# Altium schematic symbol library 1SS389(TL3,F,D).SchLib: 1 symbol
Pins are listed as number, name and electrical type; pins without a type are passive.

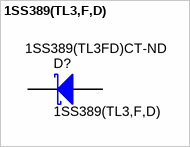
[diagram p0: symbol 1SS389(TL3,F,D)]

## 1SS389(TL3,F,D)
designator D?  Supplier Part Number: 1SS389(TL3FD)CT-ND
DIODE SCHOTTKY 10V 0.1A ESC; Manufacturer: Toshiba Semiconductor and Storage; U/M: EA; Vf_V: 0.38; Value: 500mV @ 100mA; Value1: 0.03A; Value2: 0.38V; Io_A: 100mA; TJmax_C: 125; Current - Reverse Leakage @ Vr: 20µA @ 10V; Speed: Small Signal =< 200mA (Io), Any Speed; Capacitance @ Vr, F: 40pF @ 0V, 1MHz
signal-integrity model Diode
footprint SOD-523 (NXP Semiconductor recommended land pattern, nominal STEP model)
pins: 1 K, 2 A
